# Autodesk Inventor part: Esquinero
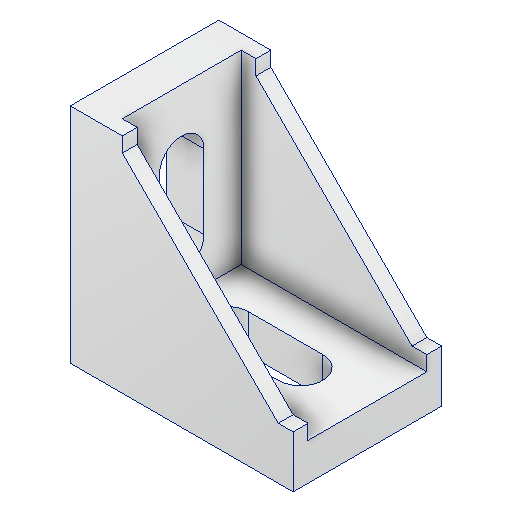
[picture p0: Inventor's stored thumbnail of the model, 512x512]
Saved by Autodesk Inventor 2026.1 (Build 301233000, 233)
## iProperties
Created: 2025-06
Part Number: Esquinero
Material: Aluminio 6061
Document SubType Name: Modeling
Designer: piero
Density: 2.7 g/cm^3
Appearance: Aluminio - Plano
Author: piero
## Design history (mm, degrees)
sketch "Boceto1"
  geometry: L1 (0, 0)-(30, 0); L2 (30, 0)-(30, -20); L3 (30, -20)-(0, -20); L4 (0, -20)-(0, 0); L5 (21, -10)-(11, -10); L6 (21, -7)-(11, -7); L7 (11, -13)-(21, -13); A1 r 3 centre (21, -10) between (21, -13) and (21, -7); A2 r 3 centre (11, -10) between (11, -7) and (11, -13); 5 further points
  constraints: 16 end point, 6 point on circle, 4 tangent, 3 midpoint, 3 parallel, 2 centre point, 2 horizontal, 1 perpendicular
  dimensions: "d0" = 30 distance of L2.end L3.end; "d1" = 20 distance of L1.end L2.end; "d2" = 10 distance of L5.start L5.end; "d3" = 6 diameter of A2; "d4" = 6 distance of point (24, -10) point (30, -10)
extrude "Extrusión1" new body sketch "Boceto1" distance "d6" = 5; taper "d7" = 0 deg
sketch "Boceto2"
  geometry: L1 (0, 0)-(20, 0) reference; L2 (0, 0)-(20, 0); L3 (20, 0)-(20, 5); L4 (20, 5)-(0, 5); L5 (0, 5)-(0, 0); 1 further point
  constraints: 8 end point, 2 parallel, 1 horizontal, 1 perpendicular
  dimensions: "d8" = 20 distance of L4.end L3.end; "d9" = 5 distance of L3.end L2.end
extrude "Extrusión2" join sketch "Boceto2" distance "d10" = 25; taper "d11" = 0 deg
sketch "Boceto3"
  geometry: L1 (6, 10)-(16, 10); L2 (6, 7)-(16, 7); L3 (16, 13)-(6, 13); L4 (25, 20)-(25, 0) reference; L5 (0, 0)-(25, 0) reference; A1 r 3 centre (6, 10) between (6, 13) and (6, 7); A2 r 3 centre (16, 10) between (16, 7) and (16, 13); 4 further points
  constraints: 8 end point, 5 point on circle, 4 tangent, 2 centre point, 2 midpoint, 1 horizontal, 1 parallel
  dimensions: "d12" = 10 distance of L1.start L1.end; "d13" = 6 diameter of A2; "d14" = 6 distance of point (25, 10) point (19, 10); "d15" = 10 distance from line of L5 point (11, 10)
extrude "Extrusión3" cut sketch "Boceto3" distance "d16" = 5; taper "d17" = 0 deg
sketch "Boceto4"
  geometry: L1 (5, 30)-(5, 5) reference; L2 (5, 5)-(30, 5) reference; L3 (5, 5)-(5, 28); L4 (5, 30)-(7, 30); L5 (7, 30)-(7, 28); L6 (30, 5)-(30, 7); L7 (30, 7)-(28, 7); L8 (28, 7)-(7, 28); 2 further points
  constraints: 12 end point, 3 perpendicular, 2 point on line, 1 horizontal, 1 vertical
  dimensions: "d18" = 2 distance of L3.end L1.start; "d19" = 2 distance of point (28, 5) L2.end; "d22" = 2 distance of L2.end L6.end
extrude "Extrusión4" join sketch "Boceto4" distance "d20" = 2; taper "d21" = 0 deg
sketch "Boceto5"
  geometry: L1 (-30, 0)-(-30, 5) reference; L2 (-30, 0)-(-30, 7) reference; L3 (-30, 5)-(-30, 7); L4 (-30, 7)-(-28, 7); L5 (-7, 30)-(-7, 28) reference; L6 (-28, 7)-(-7, 28); L7 (-7, 28)-(-7, 30); L8 (-7, 30)-(-5, 30); L9 (-5, 30)-(-5, 5); L10 (-5, 5)-(-30, 5); 1 further point
  constraints: 14 end point, 4 perpendicular, 1 collinear, 1 point on line, 1 vertical
  dimensions: "d23" = 2 distance of L2.end L4.end
extrude "Extrusión5" join sketch "Boceto5" distance "d24" = 2; taper "d25" = 0 deg
node "Sólido1"
